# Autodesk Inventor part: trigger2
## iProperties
Created: 2010-11
Part Number: trigger2
Document SubType Name: Modeling
Designer: ROBERT
Density: 1 g/cm^3
Author: ROBERT
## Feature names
1. Extrusion1
2. Extrusion2
3. Extrusion3
4. Extrusion4
5. TaggingFeature1
